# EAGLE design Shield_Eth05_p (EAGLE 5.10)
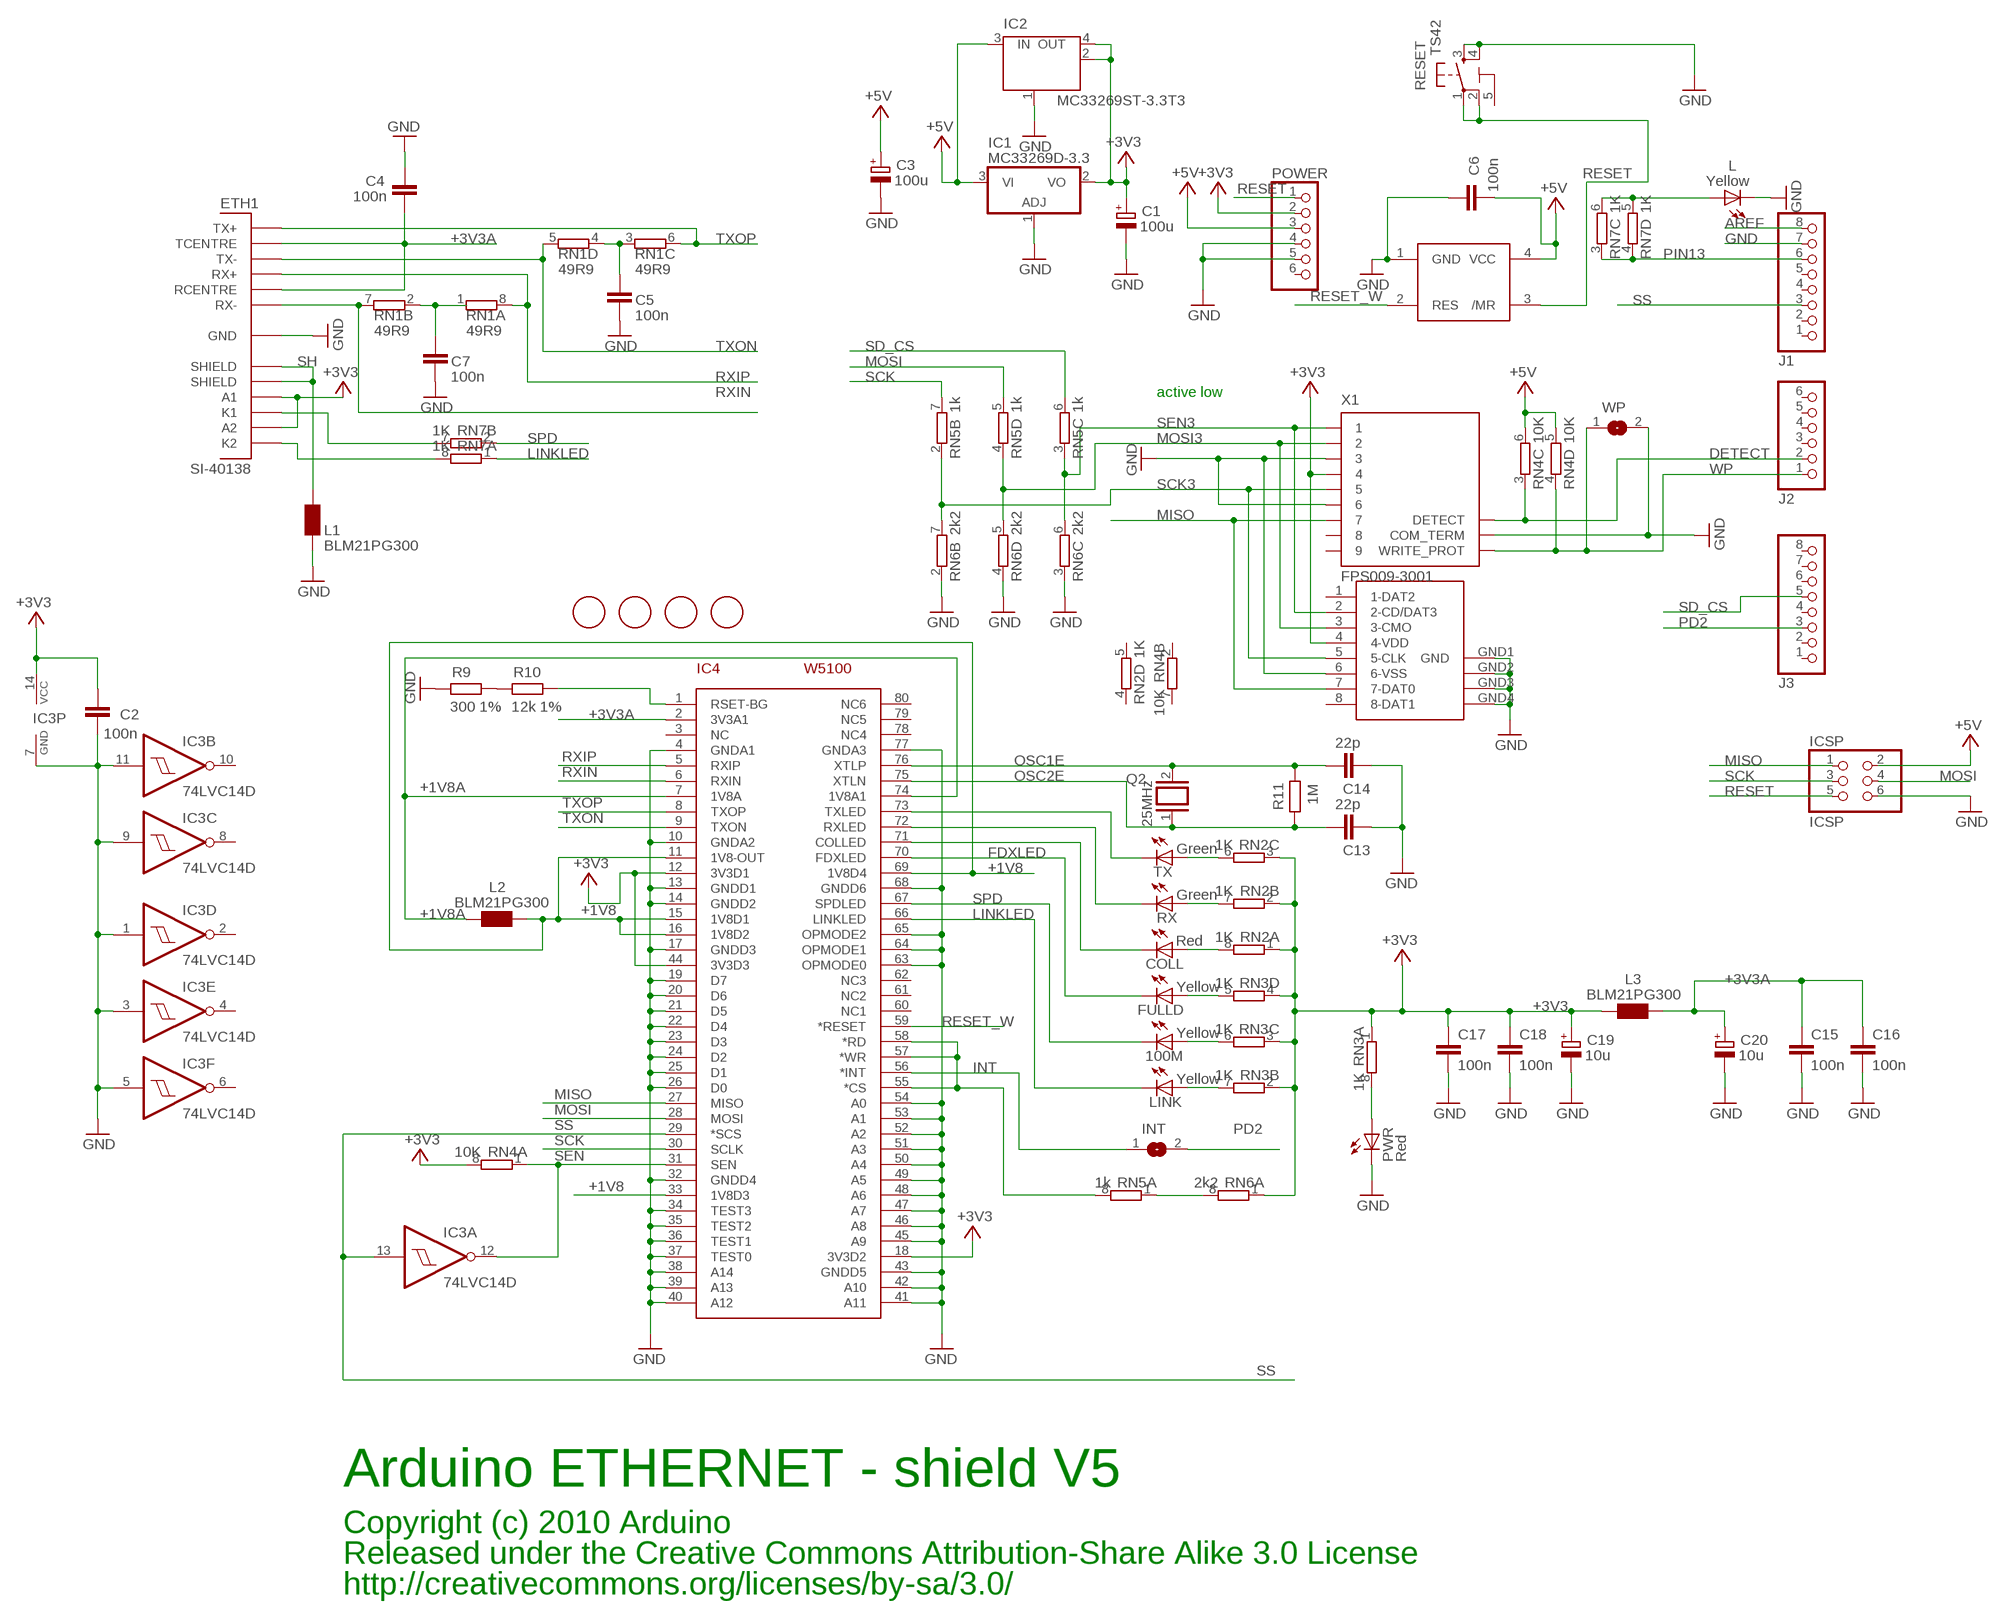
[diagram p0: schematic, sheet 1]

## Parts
100M  Yellow  LEDCHIPLED_0805  [CHIPLED_0805]
C1  100u  CPOL-EUD  [PANASONIC_D]
C2  100n  C-EUC0603  [C0603]
C3  100u  CPOL-EUD  [PANASONIC_D]
C4  100n  C-EUC0603  [C0603]
C5  100n  C-EUC0603  [C0603]
C6  100n  C-EUC0603  [C0603]
C7  100n  C-EUC0603  [C0603]
C13  22p  C-EUC0603  [C0603]
C14  22p  C-EUC0603  [C0603]
C15  100n  C-EUC0603  [C0603]
C16  100n  C-EUC0603  [C0603]
C17  100n  C-EUC0603  [C0603]
C18  100n  C-EUC0603  [C0603]
C19  10u  CPOL-EUSMCB  [SMC_B]
C20  10u  CPOL-EUSMCB  [SMC_B]
COLL  Red  LEDCHIPLED_0805  [CHIPLED_0805]
ETH1  SI-40138  [SI40138]
F1  FIDUCIALMOUNT  [FIDUCIA-MOUNT]
F2  FIDUCIALMOUNT  [FIDUCIA-MOUNT]
F3  FIDUCIALMOUNT  [FIDUCIA-MOUNT]
F4  FIDUCIALMOUNT  [FIDUCIA-MOUNT]
FULLD  Yellow  LEDCHIPLED_0805  [CHIPLED_0805]
IC1  MC33269D-3.3  [DPACK]
IC2  MC33269ST-3.3T3  [SOT223]
IC3  74LVC14D  74LS14D  [SO14]
IC4  W5100  [SQFP-S-10X10-80]
ICSP  ICSP  PINHD-2X3  [2X03]
INT  SJ  [SJ]
J1  PINHD-1X8  [1X08]
J2  PINHD-1X6  [1X06]
J3  PINHD-1X8  [1X08]
L  Yellow  LEDCHIPLED_0805  [CHIPLED_0805]
L1  BLM21PG300  WE-CBF_0805  [0805]
L2  BLM21PG300  WE-CBF_0805  [0805]
L3  BLM21PG300  WE-CBF_0805  [0805]
LINK  Yellow  LEDCHIPLED_0805  [CHIPLED_0805]
POWER  PINHD-1X6  [1X06]
PWR  Red  LEDCHIPLED_0805  [CHIPLED_0805]
Q2  25MHz  XTAL/S  [QS]
R9  300 1%  R-EU_R0603  [R0603]
R10  12k 1%  R-EU_R0603  [R0603]
R11  1M  R-EU_R0603  [R0603]
RESET  TS42  [TS42]
RN1  49R9  4R-NCAY16  [CAY16]
RN2  1K  4R-NCAY16  [CAY16]
RN3  1K  4R-NCAY16  [CAY16]
RN4  10K  4R-NCAY16  [CAY16]
RN5  1k  4R-NCAY16  [CAY16]
RN6  2k2  4R-NCAY16  [CAY16]
RN7  1K  4R-NCAY16  [CAY16]
RX  Green  LEDCHIPLED_0805  [CHIPLED_0805]
TX  Green  LEDCHIPLED_0805  [CHIPLED_0805]
U2  STM812  [SOT143]
WP  SJ  [SJ]
X1  FPS009-3001  [FPS009-3000]
X2  SDCARD-15TW-8821  [SDCARD-15TW-8821]

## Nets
+1V8 [power]: IC4.11(1V8-OUT) IC4.15(1V8D1) IC4.16(1V8D2) IC4.33(1V8D3) IC4.69(1V8D4) L2.1
+1V8A [power]: IC4.7(1V8A) IC4.74(1V8A1) L2.2
+3V3 [power]: C1.+ C2.2 C17.1 C18.1 C19.+ ETH1.9(A1) ETH1.11(A2) IC1.2(VO) IC2.2(OUT) IC2.4(OUT) IC3.14(P:VCC) IC4.12(3V3D1) IC4.18(3V3D2) IC4.44(3V3D3) L3.2 POWER.2 RN2.1 RN2.2 RN2.3 RN3.1 RN3.2 RN3.3 RN3.4 RN4.8 RN6.1 X1.4 X2.4(4-VDD)
+3V3A [power]: C4.1 C15.1 C16.1 C20.+ ETH1.2(TCENTRE) ETH1.5(RCENTRE) IC4.2(3V3A1) L3.1
+5V [power]: C3.+ C6.1 IC1.3(VI) IC2.3(IN) ICSP.2 POWER.3 RN4.5 RN4.6 U2.4(VCC)
AREF: J1.8
DETECT: J2.2 RN4.3 X1.DETECT
FDXLED: FULLD.C IC4.70(FDXLED)
GND [power]: C1.- C2.1 C3.- C4.2 C5.1 C6.2 C7.1 C13.1 C14.1 C15.2 C16.2 C17.2 C18.2 C19.- C20.- ETH1.8(GND) IC1.1(ADJ) IC2.1(GND/ADJ) IC3.1(D:I) IC3.3(E:I) IC3.5(F:I) IC3.7(P:GND) IC3.9(C:I) IC3.11(B:I) IC4.4(GNDA1) IC4.10(GNDA2) IC4.13(GNDD1) IC4.14(GNDD2) IC4.17(GNDD3) IC4.19(D7) IC4.20(D6) IC4.21(D5) IC4.22(D4) IC4.23(D3) IC4.24(D2) IC4.25(D1) IC4.26(D0) IC4.32(GNDD4) IC4.34(TEST3) IC4.35(TEST2) IC4.36(TEST1) IC4.37(TEST0) IC4.38(A14) IC4.39(A13) IC4.40(A12) IC4.41(A11) IC4.42(A10) IC4.43(GNDD5) IC4.45(A9) IC4.46(A8) IC4.47(A7) IC4.48(A6) IC4.49(A5) IC4.50(A4) IC4.51(A3) IC4.52(A2) IC4.53(A1) IC4.54(A0) IC4.63(OPMODE0) IC4.64(OPMODE1) IC4.65(OPMODE2) IC4.68(GNDD6) IC4.77(GNDA3) ICSP.6 J1.7 L1.1 L.C POWER.4 POWER.5 PWR.C R9.2 RESET.3 RESET.4 RN6.2 RN6.3 RN6.4 U2.1(GND) WP.2 X1.3 X1.6 X1.COM_TERM X2.6(6-VSS) X2.GND1(GND) X2.GND2(GND1) X2.GND3(GND2) X2.GND4(GND3)
INT: IC4.56(*INT) INT.1
LINKLED: IC4.66(LINKLED) LINK.C RN7.1
MISO: IC4.27(MISO) ICSP.1 X1.7 X2.7(7-DAT0)
MOSI: IC4.28(MOSI) ICSP.4 RN5.5
MOSI3: RN5.4 RN6.5 X1.2 X2.3(3-CMO)
N$1: PWR.A RN3.8
N$2: L.A RN7.5 RN7.6
N$3: C5.2 RN1.3 RN1.4
N$4: IC4.55(*CS) IC4.57(*WR) IC4.58(*RD) RN5.8
N$6: IC4.73(TXLED) TX.C
N$7: IC4.72(RXLED) RX.C
N$8: COLL.C IC4.71(COLLED)
N$9: RN2.6 TX.A
N$10: RN5.1 RN6.8
N$13: ETH1.10(K1) RN7.7
N$14: ETH1.12(K2) RN7.8
N$22: RN2.7 RX.A
N$23: COLL.A RN2.8
N$24: FULLD.A RN3.5
N$25: 100M.A RN3.6
N$26: LINK.A RN3.7
N$29: C7.2 RN1.1 RN1.2
N$30: R9.1 R10.2
N$31: IC4.1(RSET-BG) R10.1
OSC1E: C14.2 IC4.76(XTLP) Q2.2 R11.2
OSC2E: C13.2 IC4.75(XTLN) Q2.1 R11.1
PD2: INT.2 J3.3
PIN13: J1.6 RN7.3 RN7.4
RESET: ICSP.5 POWER.1 RESET.1 RESET.2 U2.3(/MR)
RESET_W: IC4.59(*RESET) U2.2(RES)
RXIN: ETH1.6(RX-) IC4.6(RXIN) RN1.7
RXIP: ETH1.4(RX+) IC4.5(RXIP) RN1.8
SCK: IC4.30(SCLK) ICSP.3 RN5.7
SCK3: RN5.2 RN6.7 X1.5 X2.5(5-CLK)
SD_CS: J3.5 RN5.6
SEN: IC3.12(A:O) IC4.31(SEN) RN4.1
SEN3: RN5.3 RN6.6 X1.1 X2.2(2-CD/DAT3)
SH: ETH1.S1(SHIELD) ETH1.S2(SHIELD) L1.2
SPD: 100M.C IC4.67(SPDLED) RN7.2
SS [power]: IC3.13(A:I) IC4.29(*SCS) J1.3
TXON: ETH1.3(TX-) IC4.9(TXON) RN1.5
TXOP: ETH1.1(TX+) IC4.8(TXOP) RN1.6
WP: J2.1 RN4.4 WP.1 X1.WRITE_PROT
Unconnected: IC3.2(D:O) IC3.4(E:O) IC3.6(F:O) IC3.8(C:O) IC3.10(B:O) IC4.3(NC) IC4.60(NC1) IC4.61(NC2) IC4.62(NC3) IC4.78(NC4) IC4.79(NC5) IC4.80(NC6) J1.1 J1.2 J1.4 J1.5 J2.3 J2.4 J2.5 J2.6 J3.1 J3.2 J3.4 J3.6 J3.7 J3.8 POWER.6 RN2.4 RN2.5 RN4.2 RN4.7 X1.8 X1.9 X2.1(1-DAT2) X2.8(8-DAT1)

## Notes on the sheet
- active low
- Arduino ETHERNET - shield V5
- Copyright (c) 2010 Arduino
- Released under the Creative Commons Attribution-Share Alike 3.0 License
- http://creativecommons.org/licenses/by-sa/3.0/

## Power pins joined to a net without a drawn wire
5-GND: RESET.5(5-GND)

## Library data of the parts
100M COLL FULLD L LINK PWR RX TX = led:LED: LED
C1 C3 C19 C20 = rcl:CPOL-EU: POLARIZED CAPACITOR, European symbol
C2 C4-C7 C13-C18 = rcl:C-EU: CAPACITOR, European symbol
ETH1 = ethernet:SI-40138: Ethernet Jack with Integrated Magnetics The Belfuse SI-10021 (Rapid order code 24-0484) is a single RJ-45 jack with integrated magnetics, suitable for Ethernet use.
F1-F4 = SmartPrj:FIDUCIALMOUNT
IC1 = linear:MC33269?*: Adjustable Output Low Dropout Voltage Regulator 800 mA Source: http://www.onsemi.com/pub/Collateral/MC33269-D.PDF
IC2 = linear:MC33269ST*: Adjustable Output Low Dropout Voltage Regulator 800 mA Source: http://www.onsemi.com/pub/Collateral/MC33269-D.PDF
IC3 = 74xx-eu:74*14: Hex schmitt trigger INVERTER
IC4 = SmartPrj:W5100
ICSP = pinhead:PINHD-2X3: PIN HEADER
INT WP = jumper:SJ: SMD solder JUMPER
J1 J3 = pinhead:PINHD-1X8: PIN HEADER
J2 POWER = pinhead:PINHD-1X6: PIN HEADER
L1-L3 = wuerth-elektronik:WE-CBF: SMD EMI Suppression Ferrite Beads
Q2 = special:XTAL/S: CRYSTAL
R9-R11 = rcl:R-EU_: RESISTOR, European symbol
RESET = st-mod v1.4:TS42: TS42 Dongnan Electronics Tact switch VDC 12V - 50mA
RN1-RN7 = resistor-dil:4R-N: Array Chip Resistor Source: RS Component / Phycomp
U2 = SmartPrj:STM812
X1 = con-yamaichi:FPS009-300*: SD Card and MMC Reader (Manual Insertion) Source: http://www.yamaichi.de/pdf/c_fps009_3000.pdf
X2 = st-mod v1.3:SDCARD-15TW-8821: SD Card SDCARD 15TW 8821

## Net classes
0 default: width 0.152 mm, drill 0.61 mm, clearance 0.152 mm
1 power: width 0.152 mm, drill 0.61 mm, clearance 0.152 mm
2 VIN: width 0.61 mm, drill 0.813 mm
3 usbvcc: width 0.508 mm, drill 0.711 mm, clearance 0.254 mm

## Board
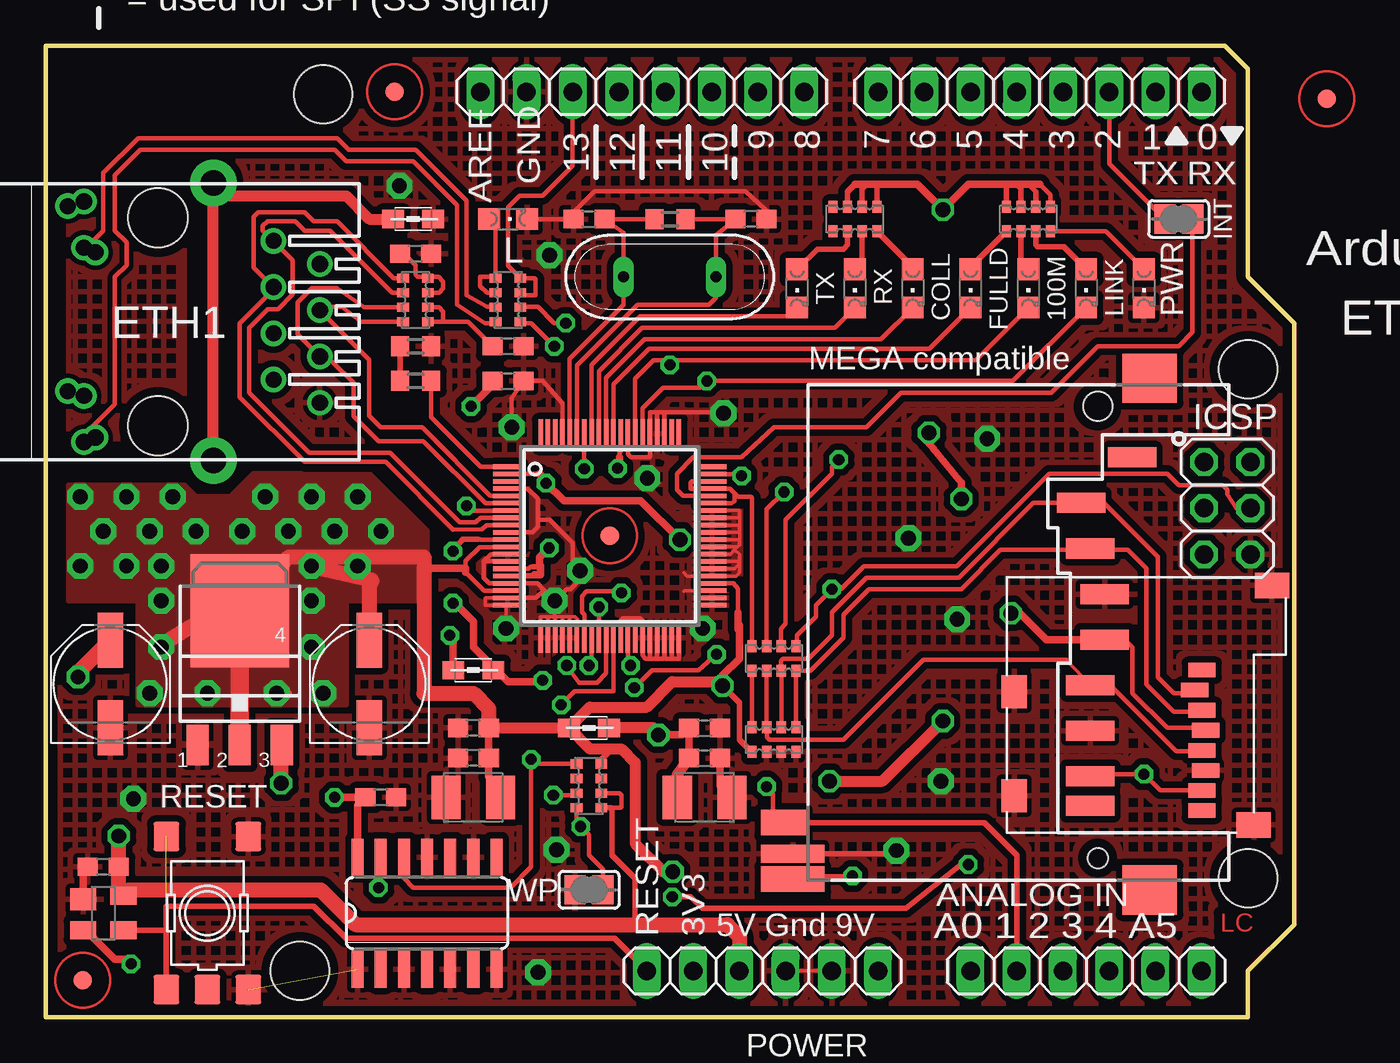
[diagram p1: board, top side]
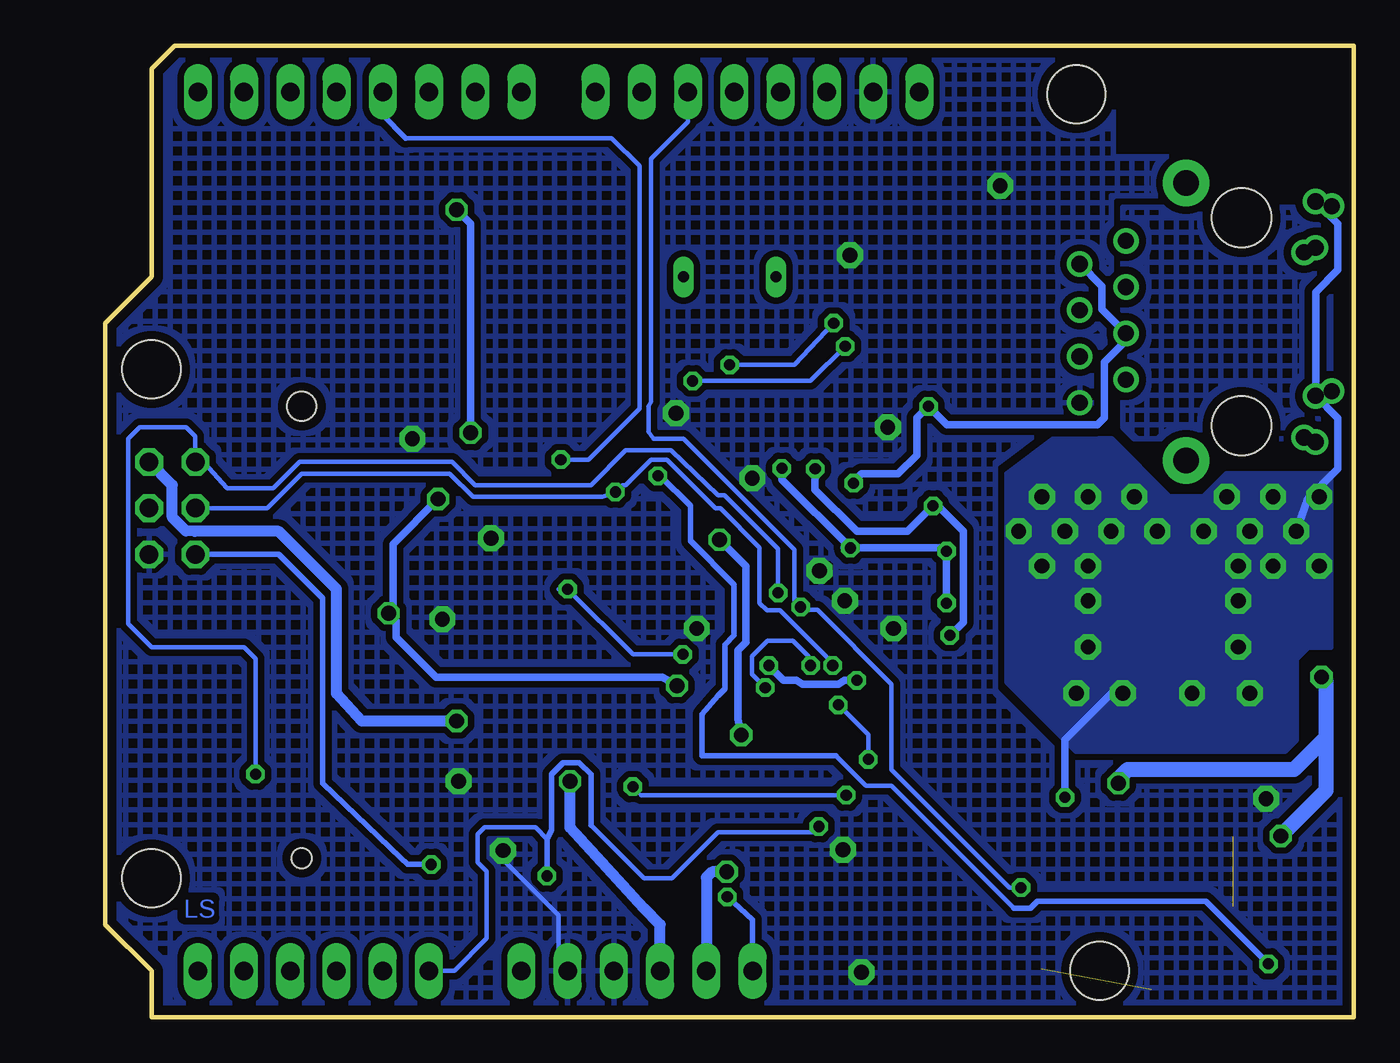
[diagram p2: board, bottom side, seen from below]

Size 68.58 x 53.34 mm. Coordinates in mm from the lower left corner, seen from the top.
Outline: 0,53.34 0,0 66.04,0 66.04,2.54 68.58,5.08 68.58,38.1 66.04,40.64 66.04,52.07 64.77,53.34 0,53.34
Copper layers (1*16): Top 0.035mm / dielectric 1.5mm / Bottom 0.035mm
Design rules "default *": minimum track width 2mil, minimum drill 2mil, track to track 2mil, track to pad 2mil, pad to pad 2mil, via to via 2mil, smd to smd 2mil, copper to edge 20mil, drill to drill 20mil, minimum pad ring 10mil, minimum via ring 8mil, stop-mask expansion 1mil, vias tented up to drill 2mil, thermal gap 10mil
Holes 3.2 mm at 66.04,35.56 66.04,7.62 15.24,50.67 13.97,2.54

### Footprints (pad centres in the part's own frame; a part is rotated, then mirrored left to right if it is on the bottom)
CHIPLED_0805 = smd 1.2 x 1.2: A 0,-1.05; C 0,1.05
PANASONIC_D = smd 3 x 1.4: + 2.4,0; - -2.4,0
C0603 = smd 1.1 x 1: 1 -0.85,0; 2 0.85,0
SMC_B = smd 1.6 x 2.4: + -1.5,0; - 1.5,0
SI40138 = drill 0.889 round: 1 -4.445,6.35; 2 -3.175,8.89; 3 -1.905,6.35; 4 -0.635,8.89; 5 0.635,6.35; 6 1.905,8.89; 7 3.175,6.35; 8 4.445,8.89; 9 -6.604,-4.064; 10 -4.064,-4.064; 11 4.064,-4.064; 12 6.604,-4.064; 13 -6.35,-4.953; 14 -3.81,-3.429; 15 3.81,-4.953; 16 6.35,-3.429 | drill 1.4 pad 2.54 round: S1 -7.62,3.048; S2 7.62,3.048 | hole 3.251: -5.715,0; 5.715,0
FIDUCIA-MOUNT = smd 1.016 x 1.016: P$1 0,0
DPACK = smd 1 x 1.6: 1 -2.28,-4.8; 3 2.28,-4.8 | smd 5.4 x 6.2: 2 0,2.5
SOT223 = smd 1.219 x 2.235: 1 -2.311,-3.099; 2 0,-3.099; 3 2.311,-3.099 | smd 3.6 x 2.2: 4 0,3.099
SO14 = smd 0.66 x 2.032: 1 -3.81,-3.073; 2 -2.54,-3.073; 3 -1.27,-3.073; 4 0,-3.073; 5 1.27,-3.073; 6 2.54,-3.073; 7 3.81,-3.073; 8 3.81,3.073; 9 2.54,3.073; 10 1.27,3.073; 11 0,3.073; 12 -1.27,3.073; 13 -2.54,3.073; 14 -3.81,3.073
SQFP-S-10X10-80 = smd 0.25 x 1.6: 1 -3.8,-5.6; 2 -3.4,-5.6; 3 -3,-5.6; 4 -2.6,-5.6; 5 -2.2,-5.6; 6 -1.8,-5.6; 7 -1.4,-5.6; 8 -1,-5.6; 9 -0.6,-5.6; 10 -0.2,-5.6; 11 0.2,-5.6; 12 0.6,-5.6; 13 1,-5.6; 14 1.4,-5.6; 15 1.8,-5.6; 16 2.2,-5.6; 17 2.6,-5.6; 18 3,-5.6; 19 3.4,-5.6; 20 3.8,-5.6; 41 3.8,5.6; 42 3.4,5.6; 43 3,5.6; 44 2.6,5.6; 45 2.2,5.6; 46 1.8,5.6; 47 1.4,5.6; 48 1,5.6; 49 0.6,5.6; 50 0.2,5.6; 51 -0.2,5.6; 52 -0.6,5.6; 53 -1,5.6; 54 -1.4,5.6; 55 -1.8,5.6; 56 -2.2,5.6; 57 -2.6,5.6; 58 -3,5.6; 59 -3.4,5.6; 60 -3.8,5.6 | smd 1.6 x 0.25: 21 5.6,-3.8; 22 5.6,-3.4; 23 5.6,-3; 24 5.6,-2.6; 25 5.6,-2.2; 26 5.6,-1.8; 27 5.6,-1.4; 28 5.6,-1; 29 5.6,-0.6; 30 5.6,-0.2; 31 5.6,0.2; 32 5.6,0.6; 33 5.6,1; 34 5.6,1.4; 35 5.6,1.8; 36 5.6,2.2; 37 5.6,2.6; 38 5.6,3; 39 5.6,3.4; 40 5.6,3.8; 61 -5.6,3.8; 62 -5.6,3.4; 63 -5.6,3; 64 -5.6,2.6; 65 -5.6,2.2; 66 -5.6,1.8; 67 -5.6,1.4; 68 -5.6,1; 69 -5.6,0.6; 70 -5.6,0.2; 71 -5.6,-0.2; 72 -5.6,-0.6; 73 -5.6,-1; 74 -5.6,-1.4; 75 -5.6,-1.8; 76 -5.6,-2.2; 77 -5.6,-2.6; 78 -5.6,-3; 79 -5.6,-3.4; 80 -5.6,-3.8
2X03 = drill 1.016 octagon: 1 -2.54,-1.27; 2 -2.54,1.27; 3 0,-1.27; 4 0,1.27; 5 2.54,-1.27; 6 2.54,1.27
SJ = smd 1.168 x 1.6: 1 -0.762,0; 2 0.762,0
1X08 = drill 1.016 long: 1 -8.89,0; 2 -6.35,0; 3 -3.81,0; 4 -1.27,0; 5 1.27,0; 6 3.81,0; 7 6.35,0; 8 8.89,0
1X06 = drill 1.016 long: 1 -6.35,0; 2 -3.81,0; 3 -1.27,0; 4 1.27,0; 5 3.81,0; 6 6.35,0
0805 = smd 1.2 x 1: 1 -1.1,0; 2 1.1,0
QS = drill 0.61 long: 1 -2.54,0; 2 2.54,0
R0603 = smd 1 x 1.1: 1 -0.85,0; 2 0.85,0
TS42 = smd 1.6 x 1.4: 1 -4.2,2.25; 2 4.2,2.25; 3 -4.2,-2.25; 4 4.2,-2.25; 5 -4.2,0
CAY16 = smd 0.5 x 0.65: 1 -1.2,-0.675; 2 -0.4,-0.675; 3 0.4,-0.675; 4 1.2,-0.675; 5 1.2,0.675; 6 0.4,0.675; 7 -0.4,0.675; 8 -1.2,0.675
SOT143 = smd 1.2 x 1.44: 1 -0.75,-1.1 | smd 1 x 1.44: 2 0.95,-1.1; 3 0.95,1.1; 4 -0.95,1.1
FPS009-3000 = smd 2.65 x 1.1: 1 -0.915,-5.3; 2 -0.415,-7.8; 3 0.385,-10.3; 4 0.385,-12.8; 5 -0.415,-15.3; 6 -0.415,-17.8; 7 -0.415,-20.3; 8 -0.415,-21.925; 9 1.885,-2.8 | smd 3.5 x 1: COM_TERM -16.75,-24.55 | smd 2.5 x 1.4: DETECT -17.25,-22.85 | smd 3 x 2.7: M1 2.85,1.55; M2 2.85,-26.55 | smd 3.5 x 1.4: WRITE_PROT -16.75,-25.95 | hole 1.6: 0,0 | hole 1.1: 0,-24.8
SDCARD-15TW-8821 = smd 0.8 x 1.5: 1 0,0; 2 1.1,-0.4; 3 2.2,0; 4 3.3,0.2; 5 4.4,0; 6 5.5,0.2; 7 6.6,0; 8 7.7,0 | smd 1.4 x 1.9: GND1 -4.66,3.85; GND2 8.49,2.85 | smd 1.8 x 1.4: GND3 1.19,-10.3; GND4 6.89,-10.3

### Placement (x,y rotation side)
100M  53.98,40.01 180 top
C1  17.78,18.29 90 top
C2  18.41,12.06 180 top
C3  3.56,18.29 90 top
C4  25.4,34.92 0 top
C5  20.32,41.91 180 top
C6  3.17,8.26 180 top
C7  25.4,36.83 180 top
C13  38.73,43.81 180 top
C14  29.84,43.81 0 top
C15  36.2,14.22 0 top
C16  36.2,15.88 0 top
C17  23.5,14.22 180 top
C18  23.5,15.88 180 top
C19  23.5,12.06 180 top
C20  36.2,12.06 0 top
COLL  47.62,40.01 180 top
ETH1  6.17,38.17 270 top
F1  30.99,26.42 0 top
F2  70.36,50.42 0 top
F3  19.18,50.8 0 top
F4  2.03,2.03 0 top
FULLD  50.8,40.01 180 top
IC1  10.67,19.81 0 top
IC2  10.67,18.03 0 top
IC3  20.95,5.71 0 top
IC4  30.99,26.42 270 top
ICSP  64.9,27.94 270 top
INT  62.23,43.81 180 top
J1  32.77,50.8 180 top
J2  57.15,2.54 0 top
J3  54.61,50.8 180 top
L  25.4,43.81 270 top
L1  20.19,43.81 180 top
L2  23.5,19.05 180 top
L3  29.84,15.88 180 top
LINK  57.15,40.01 180 top
POWER  39.37,2.54 0 top
PWR  60.33,40.01 180 top
Q2  34.29,40.64 180 top
R9  20.32,36.83 0 top
R10  20.32,34.92 180 top
R11  34.29,43.81 180 top
RESET  8.89,5.71 90 top
RN1  20.32,39.37 90 top
RN2  44.45,43.81 180 top
RN3  53.98,43.81 180 top
RN4  29.84,12.7 270 top
RN5  40.01,19.68 0 top
RN6  40.01,15.24 0 top
RN7  25.4,39.37 90 top
RX  44.45,40.01 180 top
TX  41.27,40.01 180 top
U2  3.17,5.71 270 top
WP  29.84,6.99 180 top
X1  57.78,33.53 0 top
X2  63.5,19.05 270 top

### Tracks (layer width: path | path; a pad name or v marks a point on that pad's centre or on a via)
+1V8  (via drill 0.61)
  Top 0.203: v31.42,30.12 31.52,30.14
  Top 0.254: 26.44,24.24 26.3,24.24 26.29,24.23 IC4.16 | 23.75,26.24 23.86,26.24 23.89,26.21 IC4.11 | v32.13,19.3 31.99,19.43 31.99,20.04 IC4.33 | 26.77,24.74 26.64,24.74 26.52,24.61 26.19,24.61 IC4.15 | 31.52,30.73 31.52,30.95 31.59,31.07 IC4.69
  Top 0.305: 26.85,24.28 26.72,24.24 26.44,24.24 | 23.75,26.24 22.91,26.24 v22.38,25.58 | 26.77,24.74 26.95,24.74 27.14,24.83 27.18,24.79
  Top 0.406: 31.52,30.14 31.52,30.73 | 26.85,24.28 27.18,24.28 27.18,24.79 | 27.3,18.41 v27.3,18.49 27.23,18.41 25.4,18.41 24.64,19.18 L2.1 24.34,19.47 23.5,20.32 23.5,21.72 22.48,22.73 v22.38,22.73 | 27.14,24.83 27.14,25.23 v27.66,25.76
  Bottom 0.406: v22.38,22.73 v22.38,25.58 22.3,25.76 v27.66,25.76 | v32.13,19.3 31.32,18.49 30.61,18.49 30.28,18.29 28.32,18.29 27.99,18.49 v27.3,18.49 | v27.66,25.76 28.02,25.76 | v31.42,30.12 31.42,29.52 v27.66,25.76
  pour Bottom (isolate 0.406, hatched): 1.27,31.75 12.06,31.75 12.7,32.38 12.7,44.45 1.27,44.45
+1V8A  (via drill 0.61)
  Top 0.203: 24.61,27.81 IC4.7
  Top 0.254: 23.39,27.81 24.61,27.81 | IC4.74 29.59,30.48
  Top 0.305: v23.11,28.07 23.39,27.81
  Top 0.406: v29.59,30.1 29.59,30.48 | L2.2 22.39,20.76 v22.2,20.95
  Bottom 0.406: v22.2,20.95 21.46,21.69 21.46,26.67 22.86,28.07 v23.11,28.07 24.51,26.67 27.3,26.67 29.59,28.96 v29.59,30.1
+3V3  (via drill 0.61, 0.81, 0.81 pad 1.42)
  Top 0.203: 24.66,25.81 IC4.12 | IC2.4 | IC2.4 IC1.2 | 58.88,20.73 X1.4
  Top 0.254: 23.06,24.43 24.08,23.42 24.61,23.42 IC4.18 | 23.06,24.64 23.06,25.04 23.82,25.81 24.66,25.81 | 38.02,22.2 38.02,23.52 37.8,23.81 37.41,23.81 IC4.44 | 38.77,14.56 RN6.1 | 59.28,20.73 59.69,20.32 59.69,17.78 61.59,15.88 64.21,15.88 X2.4 | 53.98,45.72 54.38,45.32 | RN3.1 55.17,45.16 54.61,45.72
  Top 0.305: RN2.3 44.05,45.32 44.45,45.72 | RN2.2 44.85,45.48 45.09,45.72 | RN2.1 45.65,45.65 45.72,45.72 | 54.38,45.32 RN3.2 | RN3.3 53.58,45.48 53.34,45.72 | RN3.4 52.77,45.65 52.7,45.72 | RN4.8 30.52,14.14 31.11,14.73 | 38.77,14.56 38.1,15.24 38.1,17.27 v37.19,18.19
  Top 0.406: 23.06,24.43 23.06,24.64 21.21,24.64 20.7,24.89 20.78,25.27 | 59.28,20.73 58.88,20.73 54.97,20.73 53.52,22.17 v53.01,22.17 | 48.51,32.13 v48.51,32.08 48.51,31.5 48.77,31.21 50.29,29.34 v50.29,28.45 | 38.02,21.59 38.02,21.29 | 38.02,21.59 38.02,22.2 | 44.45,45.72 45.09,45.72 45.72,45.72 47.88,45.72 v49.28,44.32 50.67,45.72 52.7,45.72 53.34,45.72 53.98,45.72 54.61,45.72 | v37.19,18.19 37.19,18.77 38.1,19.68 38.1,21.51 38.02,21.59 | C18.1 C17.1 24.34,13.19 24.82,12.71 | IC3.14 17.14,11.64 C2.2 v15.88,12.06 | v12.7,17.78 13.34,17.78 | IC2.2 10.79,14.81
  Top 0.61: C19.+ 24.82,12.71 24.77,12.93 | L3.2 29.89,14.73 31.11,14.73 31.62,14.73 32.38,13.97 32.38,9.53 33.93,7.98 v34.44,7.98 | v37.19,18.19 37.24,18.19 36.83,18.41 34.42,18.41 33.02,17.02 29.89,17.02 L3.2 | C18.1 L3.2
  Top 0.813: 6.73,20.68 7.98,21.44 IC1.2 13.36,25.27 20.78,25.27 20.78,17.78 23.5,17.78 24.34,16.93 C18.1 | C1.+ 17.78,23.75 17.91,23.88 17.91,24 v14.61,24.77
  Top 1.016: IC2.2 IC2.4
  Bottom 0.406: v50.29,28.45 52.78,25.96 52.78,22.66 v53.01,22.17 52.6,21.77 52.6,20.85 50.42,18.67 37.97,18.67 v37.19,18.19 | v48.51,32.08 48.51,43.56 v49.28,44.32 | v3.17,26.67 2.54,28.45 0.89,30.1 0.89,32.89 ETH1.11 2.11,39.8 0.89,41.02 0.89,43.56 ETH1.9 | v15.88,12.06 15.88,15.24 13.34,17.78 v12.7,17.78
  Bottom 0.61: v34.44,7.98 35.26,7.98 35.56,7.67 POWER.2
  other vias: 14.61,28.57 15.88,26.67 14.61,20.32 6.35,20.32 6.35,22.86 6.35,24.77 8.26,26.67 13.34,26.67 4.45,24.77 8.89,17.78 14.61,22.86 10.79,26.67 17.14,24.77 5.71,26.67 18.41,26.67 17.14,28.57 12.06,28.57 6.99,28.57 4.45,28.57 1.91,28.57 1.91,24.77 5.71,17.78 15.24,17.78
  pour Top (isolate 0.406, no thermals): 5.08,17.14 16.51,17.14 16.51,22.86 20.95,22.86 20.95,26.67 17.78,29.84 11.43,29.84 10.16,28.57 8.26,28.57 7.62,29.21 1.27,29.21 1.27,22.86 5.08,22.86
  pour Bottom (isolate 0.406, no thermals): 3.17,15.24 3.81,14.61 15.24,14.61 19.05,18.41 19.05,29.84 16.51,31.75 13.34,31.75 10.16,28.57 8.26,28.57 6.99,29.84 1.27,29.84 1.27,20.32 2.54,20.32 3.17,19.68
+3V3A  (via drill 0.61, 0.81)
  Top 0.254: v27.48,29.31 27.18,29.72 27.18,29.82 26.2,29.82 IC4.2
  Top 0.406: v34.85,26.21 32.69,28.35 28.47,28.35 v27.48,29.31 27.13,29.82 27.18,29.77 | 24.64,35.18 C4.1 24.55,34.71 v23.37,33.53 | C15.1 C16.1 34.96,15.49 v33.66,15.49
  Top 0.61: C20.+ 34.7,13.32 C15.1 | L3.1 33.4,15.88 v33.66,15.49
  Bottom 0.406: v33.66,15.49 33.83,16.36 33.83,20.14 33.4,20.57 33.4,24.77 v34.85,26.21 | ETH1.5 | ETH1.2 13.84,40.13 13.84,38.86 ETH1.5 | v27.48,29.31 27.48,29.41 27.05,29.84 25.04,29.82 24,30.86 24,32.89 v23.37,33.53 22.35,32.51 14.1,32.51 13.72,32.89 13.72,35.94 12.52,37.13 ETH1.5
+5V  (via drill 0.81, 0.81 pad 1.02)
  Top 0.203: IC1.3 IC2.3
  Top 0.254: RN4.6 31.52,12.3 31.62,12.19 31.62,11.56 31.57,11.5 RN4.5
  Top 0.305: RN4.5 31.05,11.5 31.11,11.43 31.11,8.89 32.38,7.62 32.38,5.08
  Top 0.406: IC1.3 13.11,15.01 | U2.4 4.03,6.92
  Top 0.61: v43.05,12.95 45.97,12.95 v49.28,16.26
  Top 0.813: v1.78,18.67 1.78,18.91 C3.+ | v12.95,12.83 IC1.3 | POWER.3 38.1,4.45 37.47,5.08 32.38,5.08 17.02,5.08 15.11,6.99 4.59,6.99 U2.4 | v4.03,9.95 C6.1 4.03,6.92
  Bottom 0.61: ICSP.2 64.9,29.21 64.9,27.43 64.16,26.7 63.65,26.67 59.05,26.67 55.88,23.5 55.88,17.78 54.48,16.26 v49.28,16.26 49.15,16.26 | v43.05,12.95 43.05,10.41 38.99,5.97 38.1,5.08 POWER.3
  Bottom 0.813: v1.78,18.67 1.52,18.41 1.52,15.37 | v12.95,12.82 v12.95,12.83 v12.94,12.83 12.94,13.09 12.45,13.59 3.3,13.59 1.52,15.37 | v4.03,9.95 1.52,12.45 1.52,15.37
DETECT  (via drill 0.61)
  Top 0.254: v39.6,12.65 39.95,12.27 39.95,11.35 X1.DETECT | v27.89,12.19 29.06,12.19 RN4.3
  Top 0.305: X1.DETECT 51.55,10.68 53.34,8.89 J2.2
  Bottom 0.203: 39.17,12.19 v39.6,12.65
  Bottom 0.254: v27.89,12.19 39.17,12.19
FDXLED
  Top 0.254: IC4.70 31.19,34.74 33.15,36.7 48.55,36.7 FULLD.C
GND  (via drill 0.81 pad 1.42)  (1 unrouted)
  Top 0.203: 33.17,19.68 IC4.36 | 24.38,23.81 24.36,23.82 | 33.6,33.2 IC4.64 | C14.1 28.8,43.99 | POWER.4 POWER.5 | 40.64,8.97 41.96,8.97 X1.COM_TERM 39.93,8.99 | IC1.1 IC2.1 | IC4.21 27.19,21.96 27.19,21.97 27.56,21.97 | 28.07,21.97 27.56,21.97 | 28.07,21.97 28.45,21.97 | 28.45,21.97 28.7,21.97 | 28.7,21.97 29.08,21.97 29.21,21.84 29.21,20.84 IC4.26 | IC4.25 28.79,21.89 28.7,21.97 | IC4.24 28.39,21.91 28.45,21.97 | IC4.23 27.99,21.89 28.07,21.97 | IC4.22 27.59,21.94 27.56,21.97 | IC4.54 38.1,27.82 38.1,27.81 38.1,27.3 | 38.1,26.92 38.1,27.3 | 38.1,26.67 38.1,26.92 | 38.1,26.29 38.1,26.67 | 38.1,26.29 38.1,25.91 38.01,25.82 | IC4.48 37.61,25.42 37.85,25.65 | 37.85,25.65 38.01,25.82 | 38.01,25.82 IC4.49 | IC4.50 38.03,26.22 38.1,26.29 | IC4.51 38.05,26.62 38.1,26.67 | IC4.52 38.01,27.02 38.1,26.92 | IC4.53 37.99,27.42 38.1,27.3 | 28.07,21.97 27.96,22.07 v27.96,22.86 | IC4.19 24.16,23.02 24.13,22.99 24.13,22.61 24.14,22.62 IC4.20 25.3,22.53 v25.3,21.34 | 38.1,24.89 38.1,24.38 37.93,24.22 IC4.45 35.22,24.22 35.05,24.38 | 38.1,24.89 38.1,25.4 37.85,25.65 | IC4.47 37.98,25.02 38.1,24.89 | IC4.46 37.82,24.62 38.1,24.89 | IC4.43 35.1,23.42 35.05,23.37
  Top 0.254: 32.4,21.89 31.73,21.89 31.59,21.75 31.59,21.61 IC4.32 | 32.4,21.89 IC4.34 | 32.4,21.89 32.66,21.89 32.79,21.77 IC4.35 32.78,19.86 32.95,19.68 33.17,19.68 33.2,19.68 | IC4.37 33.59,19.81 33.48,19.68 | 33.2,19.68 33.48,19.68 | IC4.36 33.2,19.68 | 24.36,23.82 24.07,24.12 24.07,25.02 | 24.07,25.02 24.61,25.02 IC4.14 | 24.38,23.81 IC4.17 27.01,23.82 27.38,23.44 | 33.6,33.2 33.19,33.2 IC4.65 33.19,30.77 33.15,30.73 32.16,30.73 31.99,30.9 IC4.68 | 33.98,33.2 33.59,33.21 IC4.64 | 33.98,33.2 IC4.63 | L.C C14.1 | 28.8,43.99 30.15,45.34 38.43,45.34 39.9,43.99 C13.1 | 33.98,33.2 37.31,33.2 v37.24,33.15 | 27.38,23.44 v27.96,22.86 28.6,23.5 28.83,23.5 29.36,24.03 v29.36,24.51 28.96,24.92 28.96,26.04 27.69,27.3 27.05,27.3 | IC4.19 26.95,23.02 27.38,23.44 | IC4.4 26.48,29.02 27.05,28.45 27.05,27.3 | IC4.10 26.74,26.62 27.05,26.92 27.05,27.3 | IC4.13 24.46,25.42 24.07,25.02 | IC4.77 28.39,33.72 27.3,34.92 C4.2 25.6,33.98 v25.6,32.38 | IC4.40 34.79,19.7 34.8,19.68 34.42,19.68 | IC4.39 34.42,20.79 34.42,19.68 | 33.99,19.76 33.99,19.73 34.04,19.68 34.42,19.68 | 33.99,19.76 IC4.38 | 33.99,19.76 33.91,19.68 33.48,19.68
  Top 0.305: 41.96,8.97 46.56,8.97 v46.74,9.14
  Top 0.406: U2.1 2.08,8.01 C6.2 | C20.- 37.05,12.71 C15.2
  Bottom 0.254: v46.74,9.14 46.74,8.64 43.69,5.59 43.69,3.05 POWER.5
  other vias: 27.69,41.83 49.17,12.95 51.71,31.75 47.4,26.29 50.06,21.84 36.09,21.34 33.05,29.59 19.43,45.64 27.05,2.46 4.83,11.99 28.07,9.19
  pour Top (isolate 0.254, rank 2, hatched): 1.27,31.75 7.62,31.75 7.62,44.45 1.27,44.45
  pour Top (isolate 0.356, rank 2, hatched): 0.51,47.24 13.21,47.24 13.21,52.83 64.52,52.83 65.53,51.82 65.53,40.13 68.07,37.59 68.07,5.59 65.53,3.05 65.53,0.51 0.51,0.51
  pour Bottom (isolate 0.356, rank 2, hatched): 0.51,47.24 13.21,47.24 13.21,52.83 64.52,52.83 65.53,51.82 65.53,40.13 68.07,37.59 68.07,5.59 65.53,3.05 65.53,0.51 0.51,0.51
INT
  Top 0.254: IC4.56 35.01,28.62 34.67,28.96 34.67,29.84 35.56,30.73 38.23,30.73 40.01,32.38 45.09,32.38 46.99,34.29 55.24,34.29 57.78,36.83 62.23,36.83 62.99,37.59 INT.1
LINKLED  (via drill 0.61)
  Top 0.254: IC4.66 32.79,33.42 33.91,34.54 35.94,34.54 v36.32,34.92 | v36.32,34.92 36.2,34.92 | v27.94,36.83 26.67,38.1 26.14,38.1 RN7.1 | v36.32,34.92 53.12,34.92 LINK.C
  Bottom 0.254: v36.32,34.92 29.84,34.92 v27.94,36.83
MISO  (via drill 0.61)
  Top 0.203: IC4.27 29.59,21.61
  Top 0.254: 29.59,21.61 29.59,22.1 29.46,22.23 29.46,23.11 29.72,23.37 31.37,23.37 v31.62,23.29 | X1.7 57.48,13.34 v60.33,13.34 61.21,12.45 X2.7
  Bottom 0.254: v31.62,23.29 31.62,25.7 34.57,28.65 34.92,28.65 37.52,31.11 40.01,31.11 41.91,29.21 48.26,29.21 49.53,30.48 57.91,30.48 59.36,29.03 61.87,29.03 62.89,30.15 ICSP.1 63.63,31.88 64.14,32.38 66.67,32.38 67.31,31.75 67.31,21.59 66.04,20.32 60.96,20.32 60.33,19.68 v60.33,13.34
MOSI  (via drill 0.61)
  Top 0.254: v29.84,19.3 29.98,19.32 29.98,20.04 IC4.28 | v32.33,18.09 33.3,19.05 35.87,19.05 v36.85,19.91 | ICSP.4 65.41,27.94 64.9,28.7 64.9,28.96 64.64,29.21 62.23,29.21 61.59,29.84 55.12,29.84 50.04,24.77 44.96,24.77 43.69,23.5 v43.18,23.5 42.31,22.62 42.31,21.99 41.27,20.95 41.27,20.43 RN5.5
  Bottom 0.254: v29.84,19.3 29.97,19.81 30.82,20.66 32.22,20.66 33.07,19.81 33.07,18.82 v32.33,18.09 | 43.69,23.5 v43.18,23.5 39.6,19.91 v36.85,19.91
MOSI3
  Top 0.203: 57.93,25.65 X1.2
  Top 0.254: RN6.5 RN5.4 42,19.01 43.81,20.83 43.81,22.1 45.21,23.5 50.29,23.5 52.45,25.65 57.93,25.65 59.44,25.65 60.45,24.64 60.45,18.29 61.98,16.76 63.41,16.76 X2.3
N$1
  Top 0.254: RN3.8 58.24,43.14 PWR.A
N$2
  Top 0.254: L.A 24.73,43.44 RN7.5 24.66,40.64 23.88,40.64 23.88,40.13 24.24,39.77 RN7.6
N$3
  Top 0.254: RN1.3 21.61,39.77 21.84,40.01 21.84,40.39 21.59,40.64 21.07,40.64 RN1.4 20.93,40.64 20.45,40.64 20.32,40.77 20.32,41.27 19.68,41.91 C5.2
N$4
  Top 0.254: IC4.58 35.51,29.42 35.43,29.34 35.43,29.02 IC4.57 36.65,29.02 37.59,29.02 37.85,28.77 | IC4.55 36.6,28.21 37.66,28.21 37.85,28.33 37.85,28.77 | 37.85,28.77 38.04,28.57 38.73,28.57 38.8,28.5 RN5.8
N$6
  Top 0.254: IC4.73 29.98,35.83 32.64,38.48 40.8,38.48 TX.C
N$7
  Top 0.254: IC4.72 30.39,35.47 32.77,37.85 43.34,37.85 RX.C
N$8
  Top 0.254: IC4.71 30.79,35.11 32.89,37.21 45.88,37.21 COLL.C
N$9
  Top 0.305: RN2.6 44.05,42.4 43.81,42.16 42.38,42.16 TX.A
N$10
  Top 0.254: RN6.8 RN5.1
N$13
  Top 0.254: ETH1.10 2.23,42.24 3.17,43.18 3.17,46.35 5.08,48.26 16,48.26 16.64,47.62 20.32,47.62 23.11,44.83 23.11,39.62 24.26,38.99 24.71,38.99 RN7.7
N$14
  Top 0.254: ETH1.12 2.11,31.95 3.81,33.66 3.81,40.64 4.45,41.27 4.45,42.55 3.81,43.18 3.81,46.23 5.21,47.62 15.88,47.62 16.51,46.99 20.19,46.99 22.61,44.58 22.61,39.12 24.13,38.1 24.66,38.1 RN7.8
N$22
  Top 0.305: RN2.7 44.85,41.45 RX.A
N$23
  Top 0.305: COLL.A 47.62,41.16 RN2.8
N$24
  Top 0.305: FULLD.A 50.8,41.16 RN3.5
N$25
  Top 0.305: RN3.6 53.58,41.45 100M.A
N$26
  Top 0.305: RN3.7 54.38,42.4 54.48,42.29 55.91,42.29 LINK.A
N$29
  Top 0.254: RN1.1 21.84,38.17 | 21.84,38.17 23.21,38.17 C7.2 | RN1.2 21.61,38.97 21.84,38.73 21.84,38.17
N$30
  Top 0.305: R10.2 R9.1
N$31
  Top 0.254: IC4.1 24.43,30.21 23.89,30.21 21.17,32.93 R10.1
OSC1E
  Top 0.254: IC4.76 28.79,36.15 31.75,39.12 Q2.2 31.75,43.05 C14.2 R11.2
OSC2E
  Top 0.254: IC4.75 29.19,35.79 32.51,39.12 36.45,39.12 36.83,39.5 Q2.1 36.83,42.93 C13.2 R11.1
PD2
  Top 0.254: J3.3 58.42,46.86 INT.2
PIN13
  Top 0.254: J1.6 28.96,46.74 27.3,45.09 26.04,45.09 25.4,44.45 25.4,41.24 RN7.4 26.85,40.57 26.92,40.51 26.92,39.62 26.22,39.62 RN7.3
RESET  (via drill 0.61 pad 1.02)  (1 unrouted)
  Top 0.305: v50.67,8.38 50.29,8.38 47.24,5.97 36.07,5.97 35.43,6.6 v34.42,6.6 | POWER.1 31.24,4.32 16.51,4.32 14.73,6.1 6.64,6.1 6.64,4.76 | RESET.1 6.64,4.76 | 6.64,4.76 U2.3
  Bottom 0.305: ICSP.5 59.05,25.4 56.64,22.99 56.64,12.83 52.35,8.76 51.97,8.38 v50.67,8.38 | POWER.1 33.02,5.33 v34.42,6.6
RESET_W  (via drill 0.61 pad 1.02)
  Top 0.254: IC4.59 38.2,29.82 v38.23,29.72
  Top 0.406: U2.2 2.22,4.76 3.81,3.17 4.45,3.17 v4.7,2.92
  Bottom 0.254: 18.67,5.97 25.4,12.7 26.8,12.7 28.45,14.35
  Bottom 0.305: v38.23,29.72 38.1,29.72 36.45,28.07 36.45,26.16 34.04,23.75 34.04,20.95 34.54,20.45 34.54,18.03 34.92,17.65 35.81,16.64 35.81,14.35 28.45,14.35 | 18.67,5.97 17.78,5.97 17.4,6.35 8.13,6.35 v4.7,2.92
RXIN
  Top 0.254: IC4.6 24.61,28.22 24.16,28.22 20.73,31.62 18.29,31.62 16.92,32.99 16.92,34.82 15.75,35.99 ETH1.6 13.84,37.49 13.84,39.24 14.61,40.01 16,40.01 17.51,38.97 RN1.7
RXIP
  Top 0.254: IC4.5 24.42,28.62 20.7,32.35 20.66,32.38 18.41,32.38 17.78,33.02 17.78,36.09 ETH1.4 15.24,38.99 16.26,38.99 17.34,38.17 RN1.8
SCK  (via drill 0.61)
  Top 0.203: 30.79,20.04 IC4.30
  Top 0.254: 30.79,20.04 30.79,18.87 30.28,18.36 29.31,18.36 v28.63,19.3 | RN5.7 39.6,27.87 v40.56,28.83
  Bottom 0.254: v28.63,19.3 28.98,19.79 31.52,22.33 32.23,22.33 32.64,22.73 32.64,25.78 34.8,27.94 35.05,27.94 37.72,30.61 38.61,30.61 40.01,29.21 40.18,29.21 v40.56,28.83 41.27,28.57 48.39,28.57 49.66,29.84 57.78,29.84 59.69,27.94 ICSP.3
SCK3
  Top 0.203: 56.06,19.63 X1.5
  Top 0.254: RN5.2 RN6.7 39.62,15.9 39.62,15.37 39.75,15.24 43.81,15.24 48.21,19.63 56.06,19.63 | X1.5 58.48,18.23 62.1,14.61 64.09,14.61 X2.5
SD_CS  (via drill 0.61 pad 1.02)
  Top 0.254: RN5.6 40.39,20.38 40.39,21.34 40.64,21.59 40.64,27.3 43.18,29.84 43.18,30.23 v43.56,30.61
  Bottom 0.254: v43.56,30.61 42.04,30.61 39.24,33.4 39.24,46.74 40.77,48.26 52.07,48.26
  Bottom 0.305: J3.5 53.34,49.53 52.07,48.26
SEN  (via drill 0.61)
  Top 0.203: 31.19,20.04 IC4.31
  Top 0.254: 31.19,20.04 31.19,17.88 29.06,17.88 v28.32,17.14 | 19.76,9.35 IC3.12 19.68,7.62 20.19,7.11 25.53,7.11 26.67,8.26 v26.67,14.15 26.68,13.9 RN4.1
  Bottom 0.254: v26.67,14.15 26.67,15.49 v28.32,17.14
SEN3
  Top 0.254: RN6.6 RN5.3 40.39,19.03 40.39,19.56 40.51,19.68 41.91,19.68 43.18,20.95 43.18,22.23 45.09,24.13 50.16,24.13 54.26,28.23 X1.1 58.13,28.23 61.09,25.27 61.09,18.67 61.98,17.78 62.93,17.78 X2.2
SH
  Top 0.61: L1.2 17.78,43.81 16.51,45.09 9.93,45.09 ETH1.S1 ETH1.S2
SPD  (via drill 0.61)
  Top 0.254: IC4.67 32.39,35.05 33.4,36.07 34.29,36.07 | 34.29,36.07 51.09,36.07 100M.C | v28.57,38.1 27.94,38.1 27.05,38.99 26.06,38.99 RN7.2 | 34.29,36.07 v34.29,35.81
  Bottom 0.254: v34.29,35.81 30.73,35.81 v28.57,38.1
SS  (via drill 0.61 pad 1.02)
  Top 0.254: v30.39,22.51 IC4.29 | IC3.13 18.41,7.24 v18.29,7.11
  Bottom 0.254: v18.29,7.11 18.92,7.11 25.4,13.59 25.4,18.29 29.46,22.35 30.23,22.35 v30.39,22.51 30.73,22.86 30.73,25.65 36.83,31.75 38.48,31.75 38.73,32.13 38.73,33.53 38.61,33.78 38.61,47.12 36.58,49.15 J1.3
TXON
  Top 0.254: IC4.9 24.22,27.02 23.98,26.77 22.39,26.76 18.67,30.48 14.22,30.48 10.67,34.04 10.67,38.1 12.65,40.08 | 12.65,40.08 12.7,40.13 | 12.65,40.08 ETH1.3 12.5,40.08 11.43,41.15 11.43,43.94 11.68,44.2 14.22,44.2 14.73,43.69 16,43.69 19.12,40.57 RN1.5
TXOP
  Top 0.254: IC4.8 24.02,27.42 23.89,27.41 23.62,27.18 22.73,27.18 18.92,30.99 14.48,30.99 11.18,34.29 11.18,37.85 12.19,38.86 12.78,38.86 13.56,39.67 13.56,41.55 12.52,42.59 ETH1.1 12.5,42.62 11.94,43.18 11.94,43.43 12.19,43.69 13.72,43.69 14.22,43.18 15.62,43.18 19.03,39.77 RN1.6
WP  (via drill 0.61, 0.61 pad 1.02)
  Top 0.254: v44.32,7.75 41.84,7.75 X1.WRITE_PROT | RN4.4 29.17,10.68 v29.39,10.46 29.84,10.01 29.84,8.89 30.61,8.13 WP.1
  Bottom 0.254: J2.1 49.4,2.54 47.62,4.32 47.62,8 48.13,8.51 48.13,10.03 47.75,10.41 44.96,10.41 44.32,9.78 | 41.91,10.54 38.99,7.62 37.47,7.62 34.92,10.16 29.69,10.16 v29.39,10.46
  Bottom 0.305: 41.91,10.54 41.91,13.34 42.55,13.97 43.43,13.97 44.07,13.34 44.07,10.29 44.32,9.78 v44.32,7.75 | v29.39,10.46 29.44,10.41

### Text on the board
Top: LC
Bottom: LS
tPlace: = used for SPI - Available in MEGA | = used for SPI (SS signal) | 9 | 8 | 7 | 6 | 5 | 4 | 3 | 2 | 1 | 0 | 13 | 12 | 11 | 10 | TM | ETH | Shield | SD | V5 | MEGA compatible
tNames: TX | RX | GND | AREF | Arduino | ANALOG IN | RESET | 3V3 | 5V Gnd 9V | A0 1 2 3 4 A5 | Copyright (c) 2010 Arduino | Released under the Creative Commons Attribution-Share Alike 3.0 License | http://creativecommons.org/licenses/by-sa/3.0/
Reference: C14 | R11 | C13 | C5 | Q2 | R10 | C7 | R9 | C4 | IC1 | C1 | C3 | C18 | C16 | C17 | C15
